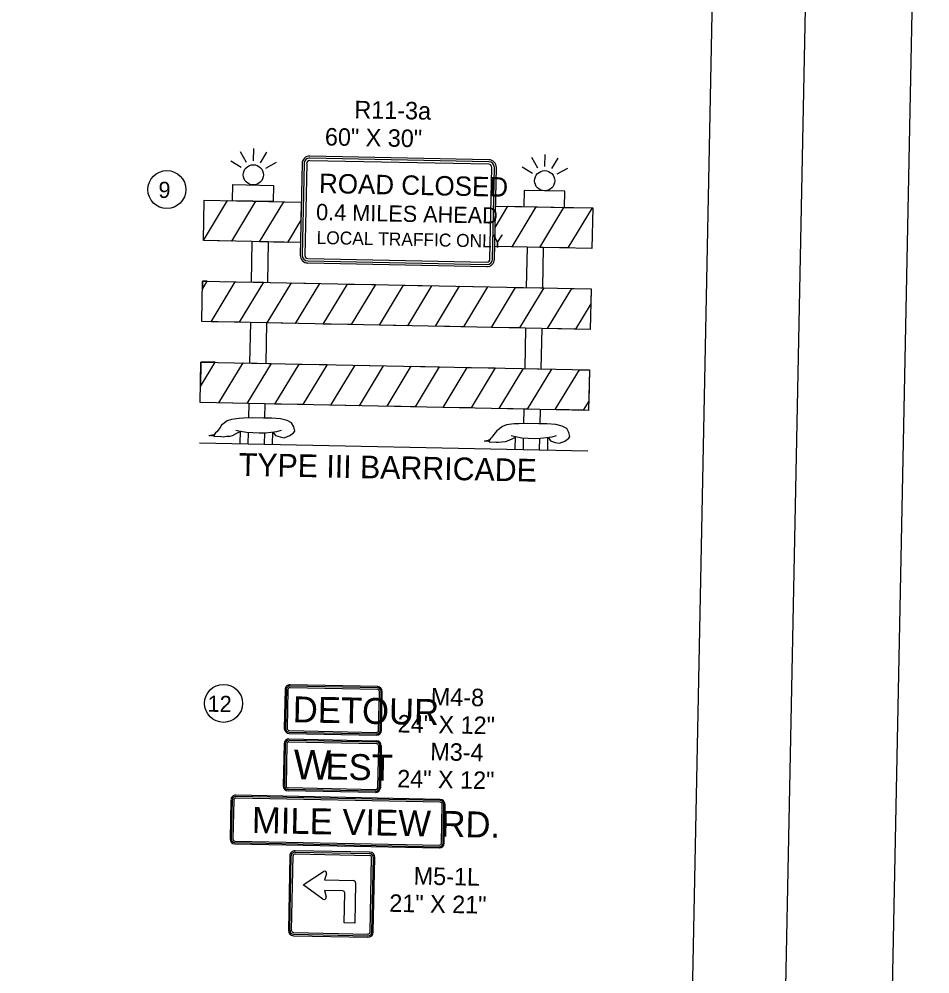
# Model space of a CAD drawing. Extents: x 299354 to 1325680, y 96128 to 228242.
# Drawn here: x 1322866 to 1325680, y 148877 to 151826 of the extents above; entities that cross this region are included whole.
import ezdxf

# ---------------------------------------------------------------- set-up
doc = ezdxf.new("R2010")
doc.units = 0
for name, color, linetype in [('CA-TEXT', 7, 'Continuous'), ('P_SGN_Cell', 7, 'Continuous'), ('PLT_Sheet_Border', 7, 'Continuous'), ('PLT_Sheet_Info', 7, 'Continuous')]:
    doc.layers.add(name, color=color, linetype=linetype)

msp = doc.modelspace()

# ---------------------------------------------------------------- linework, layer by layer
at = {"layer": 'CA-TEXT'}
for centre in [(1323322.9, 151299.5), (1323497.9, 149712.9)]:
    msp.add_circle(centre, 58.6, dxfattribs=at)
at = {"layer": 'P_SGN_Cell'}
for p, q in [((1323568.8, 151383.4), (1323550.7, 151416.2)), ((1323590.7, 151388.8), (1323591.5, 151426.3)), ((1323612.5, 151382.5), (1323631.9, 151414.6)), ((1324490.6, 151370.7), (1324491.3, 151408.2)), ((1323552.4, 151367.7), (1323520.3, 151387.1)), ((1323628.2, 151366.1), (1323661, 151384.2)), ((1323740.5, 151379.9), (1323734.8, 151096.7)), ((1323746.8, 151379.6), (1323741.1, 151096.6)), ((1323754.6, 151379.5), (1323748.9, 151096.4)), ((1324317.3, 151377.7), (1323764.1, 151388.8)), ((1324317.5, 151385.5), (1323764.3, 151396.7)), ((1324317.6, 151391.8), (1323764.4, 151402.9)), ((1324468.6, 151365.3), (1324450.5, 151398.1)), ((1324512.3, 151364.4), (1324531.7, 151396.5)), ((1324320.8, 151084.9), (1324326.5, 151368.1)), ((1324328.6, 151084.8), (1324334.3, 151368)), ((1324334.9, 151084.6), (1324340.6, 151367.9)), ((1324452.2, 151349.6), (1324420.2, 151369)), ((1324528, 151348), (1324560.9, 151366.1)), ((1323585.7, 151138.8), (1323583.2, 151013.9)), ((1323635.7, 151137.8), (1323633.2, 151012.9)), ((1324435.5, 151121.7), (1324433, 150996.8)), ((1324485.5, 151120.7), (1324483, 150995.7)), ((1323758.1, 151086.9), (1324311.2, 151075.7)), ((1323757.8, 151072.8), (1324311, 151061.7)), ((1323757.9, 151079), (1324311.1, 151067.9)), ((1323580.7, 150888.9), (1323578.2, 150763.9)), ((1323630.7, 150887.9), (1323628.2, 150762.9)), ((1324430.5, 150871.8), (1324428, 150746.8)), ((1324480.5, 150870.8), (1324478, 150745.8)), ((1323575.7, 150638.9), (1323574.8, 150594.8)), ((1323625.6, 150637.9), (1323624.8, 150594.9)), ((1324425.5, 150621.8), (1324424.6, 150577.6)), ((1324475.5, 150620.8), (1324474.6, 150576.6)), ((1323548.9, 150554.1), (1323548.1, 150514.5)), ((1323648.9, 150551.1), (1323648.1, 150512.5)), ((1323573.9, 150549.8), (1323573.1, 150514)), ((1323623.9, 150548.8), (1323623.1, 150513)), ((1324398.8, 150536.9), (1324398, 150497.4)), ((1324423.7, 150532.7), (1324423, 150496.9)), ((1324473.7, 150532.2), (1324473, 150495.8)), ((1324498.7, 150534), (1324498, 150495.3)), ((1323423.2, 150517), (1324622.9, 150492.8)), ((1323684.9, 149588.3), (1323682.3, 149458.3)), ((1323688.6, 149588.2), (1323686, 149458.2)), ((1323693.6, 149588.1), (1323691, 149458.1)), ((1323700, 149603), (1323970.1, 149597.5)), ((1323700, 149594.2), (1323970, 149588.8)), ((1323700.1, 149599.2), (1323970.1, 149593.8)), ((1323976.1, 149582.4), (1323973.5, 149452.4)), ((1323981.1, 149582.3), (1323978.5, 149452.3)), ((1323984.8, 149582.2), (1323982.2, 149452.3)), ((1323966.9, 149437.6), (1323697, 149443)), ((1323967, 149441.3), (1323697.1, 149446.7)), ((1323967.1, 149446.3), (1323697.2, 149451.7)), ((1323719.3, 149253.6), (1323949, 149249)), ((1323949.1, 149253.3), (1323719.4, 149258)), ((1323702.7, 149241.9), (1323698.1, 149012.2)), ((1323702.4, 149012.2), (1323707.1, 149241.8)), ((1323707.9, 149012), (1323712.5, 149241.7)), ((1323719.2, 149248.1), (1323948.9, 149243.5)), ((1323950.7, 149007.2), (1323955.3, 149236.8)), ((1323956.1, 149007), (1323960.8, 149236.7)), ((1323960.5, 149007), (1323965.1, 149236.6)), ((1323743.6, 149152.5), (1323806.3, 149193.8)), ((1323816.2, 149186.3), (1323810.1, 149167.5)), ((1323810.1, 149167.5), (1323899.2, 149165.7)), ((1323804.6, 149108.6), (1323743.6, 149152.5)), ((1323905.6, 149159), (1323903.1, 149034.4)), ((1323866.8, 149133.6), (1323809.4, 149134.7)), ((1323809.4, 149134.7), (1323814.7, 149115.7)), ((1323870.3, 149035), (1323872.2, 149128)), ((1323903.1, 149034.4), (1323870.3, 149035)), ((1323714.1, 148995.5), (1323943.8, 148990.9)), ((1323714.2, 148999.9), (1323943.9, 148995.3)), ((1323714.3, 149005.4), (1323944, 149000.7))]:
    msp.add_line(p, q, dxfattribs=at)
for points in [[(1323526.8, 151315.1), (1323651.7, 151312.5), (1323650.7, 151262.6), (1323525.7, 151265.1)], [(1324551.5, 151294.4), (1324426.6, 151296.9), (1324425.6, 151247), (1324550.5, 151244.4)], [(1323435.7, 151141.9), (1323510.4, 151265.4), (1323597, 151263.6), (1323522.3, 151140.1)], [(1324474.8, 151120.9), (1324549.4, 151244.5), (1324636, 151242.7), (1324561.4, 151119.2)], [(1323433.2, 151016.9), (1324633, 150992.7), (1324630.5, 150867.8), (1323430.7, 150891.9)], [(1323447.7, 151016.6), (1323433.2, 151016.9), (1323432.7, 150991.9)], [(1323459.6, 150891.3), (1323534.2, 151014.8), (1323620.8, 151013.1), (1323546.2, 150889.6)], [(1323632.7, 150887.8), (1323707.4, 151011.4), (1323794, 151009.6), (1323719.3, 150886.1)], [(1323805.9, 150884.4), (1323880.6, 151007.9), (1323967.2, 151006.1), (1323892.5, 150882.6)], [(1323979.1, 150880.9), (1324053.8, 151004.4), (1324140.3, 151002.6), (1324065.7, 150879.1)], [(1324152.3, 150877.4), (1324226.9, 151000.9), (1324313.5, 150999.2), (1324238.8, 150875.6)], [(1324325.4, 150873.9), (1324400.1, 150997.4), (1324486.7, 150995.7), (1324412, 150872.2)], [(1324498.6, 150870.4), (1324573.3, 150993.9), (1324633, 150992.7), (1324632.1, 150946.2), (1324585.2, 150868.7)], [(1323428.2, 150766.9), (1324628, 150742.8), (1324625.4, 150617.8), (1323425.7, 150642)], [(1323471.5, 150766.1), (1323428.2, 150766.9), (1323426.7, 150691.9)], [(1323483.4, 150640.8), (1323558.1, 150764.3), (1323644.7, 150762.6), (1323570, 150639.1)], [(1323656.6, 150637.3), (1323731.2, 150760.8), (1323817.8, 150759.1), (1323743.2, 150635.6)], [(1323829.7, 150633.8), (1323904.4, 150757.3), (1323991, 150755.6), (1323916.3, 150632.1)], [(1324002.9, 150630.3), (1324077.6, 150753.9), (1324164.2, 150752.1), (1324089.5, 150628.6)], [(1324176.1, 150626.9), (1324250.8, 150750.4), (1324337.3, 150748.6), (1324262.7, 150625.1)], [(1324349.3, 150623.4), (1324423.9, 150746.9), (1324510.5, 150745.1), (1324435.8, 150621.6)], [(1324609, 150618.1), (1324522.4, 150619.9), (1324597.1, 150743.4), (1324628, 150742.8), (1324626, 150646.3)]]:
    msp.add_lwpolyline(points, close=True, dxfattribs=at)
for points in [[(1323735.6, 151135.8), (1323435.7, 151141.9), (1323438.3, 151266.8), (1323738.1, 151260.8)], [(1323737, 151205.3), (1323695.5, 151136.6), (1323608.9, 151138.4), (1323683.6, 151261.9), (1323738.1, 151260.8)], [(1323738.1, 151260.8), (1323735.6, 151135.8)], [(1323738.1, 151260.8), (1323737, 151205.3)], [(1324335.7, 151123.7), (1324338.2, 151248.7)], [(1324338.2, 151248.7), (1324638, 151242.7), (1324635.5, 151117.7), (1324335.7, 151123.7)], [(1324336.9, 151182.7), (1324376.3, 151247.9), (1324462.9, 151246.2), (1324388.2, 151122.7), (1324335.7, 151123.7)], [(1324335.7, 151123.7), (1324336.9, 151182.7)], [(1323651.4, 150549.8), (1323658.1, 150540.5), (1323672.8, 150535.6), (1323685.3, 150533.1), (1323702.6, 150539.6), (1323714.2, 150548.5), (1323717.7, 150553.8), (1323714.5, 150566.8), (1323707.9, 150579.1), (1323694.4, 150586.2), (1323673.9, 150591.2), (1323646.6, 150593.3), (1323621.5, 150593.8), (1323587.2, 150594.4), (1323559.8, 150593.5), (1323546.1, 150593), (1323522, 150589.7), (1323509.4, 150585.4), (1323492, 150572), (1323487.3, 150565.3), (1323476.8, 150551.8), (1323473.3, 150548.8), (1323467.4, 150539.8)], [(1323536.2, 150556.7), (1323549.3, 150554)], [(1323549.8, 150553.9), (1323569.2, 150549.9), (1323608, 150548.4), (1323627.4, 150548.7), (1323662.9, 150552.6), (1323676.6, 150556.9)], [(1324501.2, 150532.7), (1324507.9, 150523.4), (1324522.6, 150518.5), (1324535.1, 150516), (1324552.4, 150522.5), (1324564, 150531.4), (1324567.5, 150536.7), (1324564.3, 150549.7), (1324557.7, 150562), (1324544.2, 150569.1), (1324523.7, 150574.1), (1324496.4, 150576.1), (1324471.3, 150576.6), (1324437, 150577.3), (1324409.6, 150576.4), (1324395.9, 150575.9), (1324371.9, 150572.6), (1324359.2, 150568.3), (1324341.8, 150554.9), (1324337.1, 150548.1), (1324326.6, 150534.7), (1324323.1, 150531.7), (1324317.2, 150522.7)], [(1323546.4, 150550.4), (1323538.3, 150546), (1323524.5, 150539.4), (1323517.6, 150537.2), (1323507.3, 150536.7), (1323497, 150535.4), (1323491.3, 150535.5), (1323487.9, 150537.1), (1323470.7, 150535.9), (1323470.8, 150537.4), (1323467.4, 150538.3), (1323452.6, 150540.1)], [(1324396.2, 150533.3), (1324388.1, 150528.9), (1324374.3, 150522.3), (1324367.4, 150520.1), (1324357.1, 150519.6), (1324346.8, 150518.3), (1324341.1, 150518.4), (1324337.7, 150520), (1324320.6, 150518.8), (1324320.6, 150520.3), (1324317.2, 150521.1), (1324302.4, 150523)], [(1324386, 150539.6), (1324399.1, 150536.9)], [(1324399.6, 150536.8), (1324419, 150532.8), (1324457.8, 150531.3), (1324477.2, 150531.6), (1324512.7, 150535.5), (1324526.5, 150539.8)], [(1323688, 149755.4), (1323685.6, 149635.4)], [(1323691.8, 149755.3), (1323689.4, 149635.4)], [(1323696.8, 149755.2), (1323694.4, 149635.3)], [(1323973.1, 149755.9), (1323703.1, 149761.4)], [(1323973.2, 149760.9), (1323703.2, 149766.4)], [(1323973.3, 149764.7), (1323703.3, 149770.1)], [(1323976.8, 149629.6), (1323979.2, 149749.5)], [(1323981.8, 149629.5), (1323984.2, 149749.4)], [(1323985.5, 149629.4), (1323988, 149749.4)], [(1323700.3, 149620.1), (1323970.2, 149614.7)], [(1323700.4, 149623.9), (1323970.3, 149618.4)], [(1323700.5, 149628.9), (1323970.4, 149623.4)], [(1323520.6, 149414.4), (1323518.1, 149294.4)], [(1323524.3, 149414.3), (1323521.9, 149294.4)], [(1323529.3, 149414.2), (1323526.9, 149294.3)], [(1324167.1, 149407.7), (1323535.7, 149420.4)], [(1324167.2, 149412.7), (1323535.8, 149425.4)], [(1324167.2, 149416.4), (1323535.9, 149429.3)], [(1324170.8, 149281.3), (1324173.2, 149401.3)], [(1324175.8, 149281.2), (1324178.2, 149401.2)], [(1324179.5, 149281.1), (1324181.9, 149401.1)], [(1323532.9, 149282.9), (1324164.3, 149270.2)], [(1323533, 149287.9), (1324164.4, 149275.2)], [(1323532.8, 149279.1), (1324165, 149266.4)]]:
    msp.add_lwpolyline(points, dxfattribs=at)
for centre in [(1323589.9, 151345), (1324489.7, 151326.9)]:
    msp.add_circle(centre, 31.2, dxfattribs=at)
for centre, radius, start, end in [((1323763.9, 151379.5), 23.4, 88.8468, 178.8468), ((1323763.9, 151379.5), 17.2, 88.8468, 178.8468), ((1323763.9, 151379.5), 9.38, 88.8468, 179.9247), ((1324317.1, 151368.3), 9.38, 358.8468, 88.8468), ((1324317.1, 151368.3), 17.2, 358.8468, 88.8468), ((1324317.1, 151368.3), 23.4, 358.8468, 88.8468), ((1323758.2, 151096.2), 23.4, 178.8468, 268.8468), ((1323758.2, 151096.2), 17.2, 178.8468, 268.8468), ((1323758.2, 151096.2), 9.38, 178.8468, 268.8468), ((1324311.4, 151085.1), 23.4, 268.8468, 358.8468), ((1324311.4, 151085.1), 17.2, 268.8468, 358.8468), ((1324311.4, 151085.1), 9.38, 268.8468, 358.8468), ((1323703, 149755.1), 15, 88.8468, 178.8468), ((1323703, 149755.1), 11.2, 88.8468, 178.8468), ((1323703, 149755.1), 6.25, 88.8468, 178.8468), ((1323703, 149755.1), 6.25, 88.8468, 96.1883), ((1323973, 149749.7), 6.25, 358.8468, 88.8468), ((1323973, 149749.7), 11.2, 358.8468, 88.8468), ((1323973, 149749.7), 15, 358.8468, 88.8468), ((1323700.6, 149635.1), 15, 178.8468, 268.8468), ((1323700.6, 149635.1), 11.2, 178.8468, 268.8468), ((1323700.6, 149635.1), 6.25, 178.8468, 268.8468), ((1323970.5, 149629.7), 15, 268.8468, 358.8468), ((1323970.5, 149629.7), 11.2, 268.8468, 358.8468), ((1323970.5, 149629.7), 6.25, 268.8468, 358.8468), ((1323699.9, 149588), 15, 89.6119, 178.8462), ((1323699.9, 149588), 11.2, 88.8462, 178.8462), ((1323699.9, 149588), 6.25, 88.8462, 178.8462), ((1323969.8, 149582.5), 6.25, 358.8462, 88.8462), ((1323969.8, 149582.5), 15, 358.8462, 88.8462), ((1323969.8, 149582.5), 11.2, 358.8462, 88.8462), ((1323697.3, 149458), 15, 178.8462, 268.8462), ((1323697.3, 149458), 11.2, 178.8462, 268.8462), ((1323697.3, 149458), 6.25, 178.8462, 268.8462), ((1323967.2, 149452.6), 15, 268.8462, 358.8462), ((1323967.2, 149452.6), 11.2, 268.8462, 358.8462), ((1323967.2, 149452.6), 6.25, 268.8462, 358.8462), ((1323535.6, 149414.3), 15, 88.8468, 178.8468), ((1323535.6, 149414.1), 11.2, 88.8468, 178.8468), ((1323535.6, 149414.1), 6.25, 88.8468, 178.8468), ((1323610, 149412.6), 6.25, 88.8468, 96.1883), ((1324166.9, 149401.4), 6.25, 358.8468, 88.8468), ((1324166.9, 149401.4), 15, 358.8468, 88.8468), ((1324166.9, 149401.4), 11.2, 358.8468, 88.8468), ((1323533.1, 149294.1), 15, 178.8468, 268.8468), ((1323533.1, 149294.1), 11.2, 178.8468, 268.8468), ((1323533.1, 149294.1), 6.25, 178.8468, 268.8468), ((1323719.1, 149241.6), 16.4, 88.8462, 178.8462), ((1323719.1, 149241.6), 12, 88.8462, 178.8462), ((1323948.7, 149236.9), 16.4, 358.8462, 88.8462), ((1324164.5, 149281.4), 15, 268.8468, 358.8468), ((1324164.5, 149281.4), 11.2, 268.8468, 358.8468), ((1324164.5, 149281.4), 6.25, 268.8468, 358.8468), ((1323719.1, 149241.6), 6.56, 88.8462, 178.8462), ((1323948.7, 149236.9), 6.56, 358.8462, 88.8462), ((1323948.7, 149236.9), 12, 358.8462, 88.8462), ((1323809.9, 149188.3), 6.56, 342.0436, 123.3759), ((1323899, 149159.2), 6.56, 358.8462, 88.8462), ((1323808.4, 149114), 6.56, 234.3166, 15.6488), ((1323866.7, 149128.1), 5.47, 358.8462, 88.8462), ((1323714.5, 149011.9), 16.4, 178.8462, 268.8462), ((1323714.5, 149011.9), 12, 178.8462, 268.8462), ((1323714.5, 149011.9), 6.56, 178.8462, 268.8462), ((1323944.1, 149007.3), 16.4, 268.8462, 358.8462), ((1323944.1, 149007.3), 12, 268.8462, 358.8462), ((1323944.1, 149007.3), 6.56, 268.8462, 358.8462)]:
    msp.add_arc(centre, radius, start, end, dxfattribs=at)
for points in [[(1323453.7, 150540.1), (1323464, 150542.1), (1323470.9, 150545)], [(1324303.5, 150522.9), (1324313.8, 150525), (1324320.7, 150527.9)]]:
    msp.add_spline(points, degree=3, dxfattribs=at)
at = {"layer": 'PLT_Sheet_Border'}
for points in [[(1308461.6, 143905.4), (1325458.1, 143563.1), (1325679.6, 154560.9), (1308683.1, 154903.2)], [(1308586.6, 144153), (1325133.2, 143819.7), (1325344.6, 154317.6), (1308798, 154650.9)]]:
    msp.add_lwpolyline(points, close=True, dxfattribs=at)
at = {"layer": 'PLT_Sheet_Info'}
msp.add_line((1324850.8, 144075.5), (1325052.2, 154073.4), dxfattribs=at)

# ---------------------------------------------------------------- texts
at = {"layer": 'CA-TEXT'}
for s, p in [('9', (1323296.3, 151274)), ('12', (1323448.2, 149687.2))]:
    msp.add_text(s, height=50, rotation=358.8468, dxfattribs=at).set_placement(p)
at = {"layer": 'P_SGN_Cell'}
for s, height, rotation, p in [('R11-3a', 54, 358.8462, (1323901.5, 151519.9)), ('60" X 30"', 54, 358.8462, (1323810.5, 151436)), ('ROAD CLOSED', 60, 358.8462, (1323792.3, 151289)), ('0.4 MILES AHEAD', 50, 358.8462, (1323783.4, 151205.5)), ('LOCAL TRAFFIC ONLY', 40, 358.8462, (1323785.1, 151131.6)), ('TYPE III BARRICADE', 70, 358.8468, (1323544.4, 150416)), ('M4-8', 54, 358.8468, (1324137.6, 149707)), ('DETOUR', 80, 358.8468, (1323711.1, 149654.7)), ('24" X 12"', 54, 358.8468, (1324035.3, 149623.3)), ('M3-4', 54, 358.8462, (1324136, 149537.3)), ('W', 91.4, 358.8462, (1323713.4, 149479.1)), ('EST', 80, 358.8462, (1323812, 149478.2)), ('24" X 12"', 54, 358.8462, (1324033.7, 149453.7)), ('MILE VIEW RD.', 80, 358.8468, (1323584.8, 149312.9)), ('M5-1L', 54, 358.8462, (1324084.7, 149153.6)), ('21" X 21"', 54, 358.8462, (1324009.3, 149069.4))]:
    msp.add_text(s, height=height, rotation=rotation, dxfattribs=at).set_placement(p)

doc.saveas('drawing.dxf')
